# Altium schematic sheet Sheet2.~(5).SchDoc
size A3; SheetNumber: 1; SheetTotal: 1
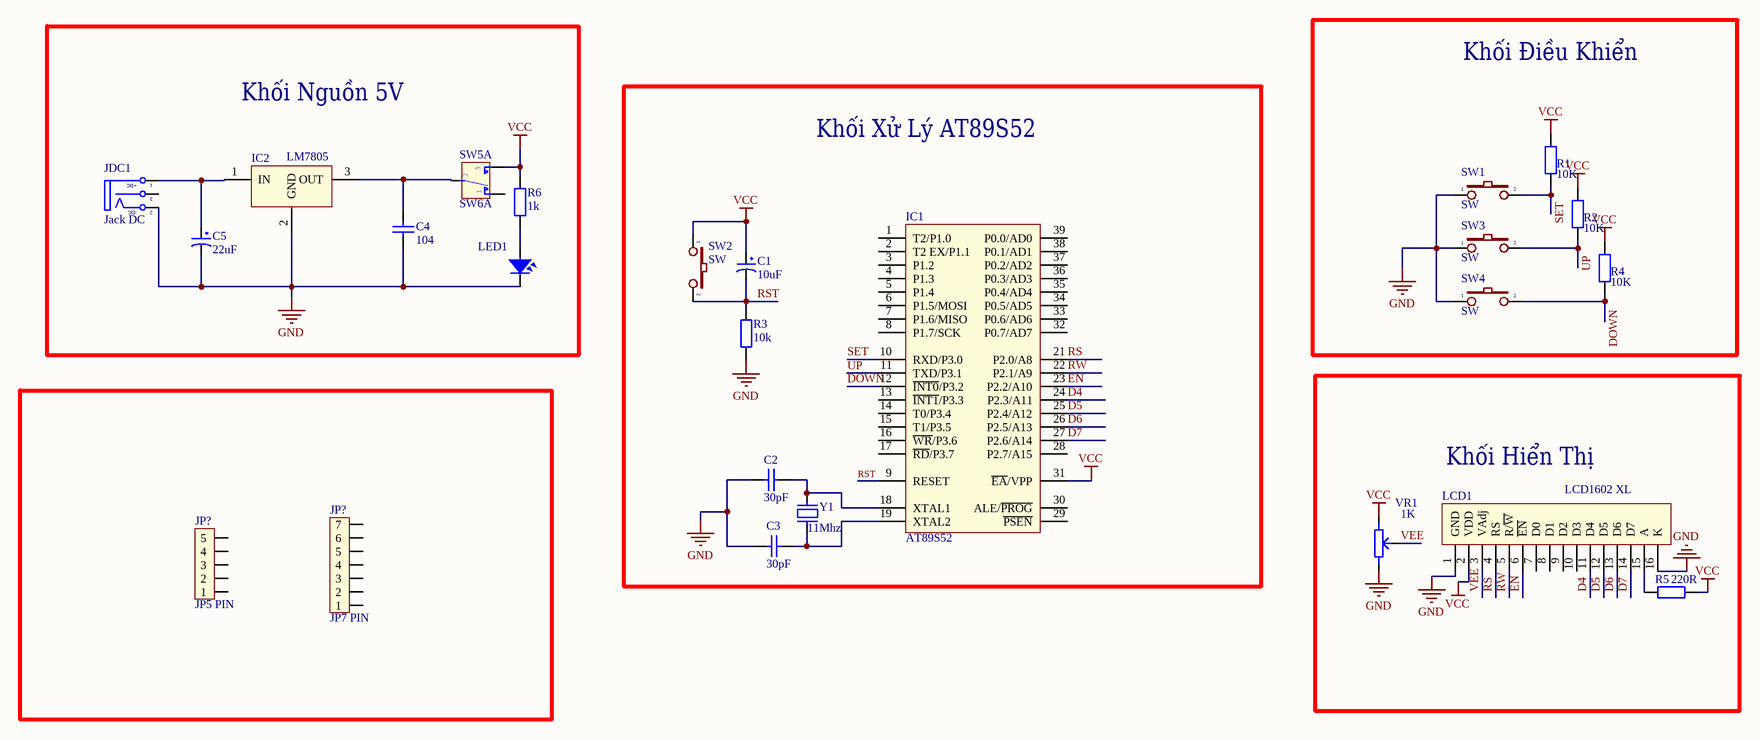
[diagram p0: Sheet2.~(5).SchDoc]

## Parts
(Parts that share a designator on the sheet are numbered #1, #2 ... from top to bottom, then left to right.)
C1  10uF  [tu hoa 4mm]
C2  30pF  [tu gom]
C3  30pF  [tu gom]
C4  104  [tu gom]
C5  22uF  [tu hoa 5mm]
IC1  AT89S52  [DIP40/W0.6]
IC2  LM7805  [QTO-220]
JDC1  Jack DC  [DC-IN]
JP?#1  JP7 PIN  [JP7_1]
JP?#2  JP5 PIN  [JP5_1]
LCD1  LCD1602 XL  [LCD1602 with Jump]
LED1  LED  [LED-5-RED]  (value not drawn)
R1  10K  [tro vach 1/4w]
R2  10K  [tro vach 1/4w]
R3  10k  [tro vach 1/4w]
R4  10K  [tro vach 1/4w]
R5  220R  [tro vach 1/4w]
R6  1k  [R1/4W]
SW1  SW  [SW2]
SW2  SW  [SW2]
SW3  SW  [SW2]
SW4  SW  [SW2]
SW5  SW6A  [SW6]  (part A of 2)
VR1  1K  [Bien Tro Tam Giac Dung]
Y1  11Mhz  [Thach Anh 2 chan cam]

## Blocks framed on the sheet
Khối Điều Khiển: R1 R2 R4 SW1 SW3 SW4
Khối Nguồn 5V: C4 C5 IC2 JDC1 LED1 R6 SW5
Khối Xử Lý AT89S52: C1-C3 IC1 R3 SW2 Y1
Khối Hiển Thị: LCD1 R5 VR1

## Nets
GND: C2.2 C3.2 C4.2 C5.2 IC1.20(GND) IC2.2(GND) JDC1.2(TN) LCD1.1(GND) LCD1.16(K) LED1.2 R3.1 SW1.1 SW3.1 SW4.1 VR1.3
VCC: C1.1 IC1.31(~{EA}/VPP) IC1.40(VCC) LCD1.2(VDD) R1.1 R2.1 R4.1 R5.1 R6.2 SW2.1 SW5.3 VR1.1
D4: IC1.24(P2.3/A11) LCD1.11(D4)
D5: IC1.25(P2.4/A12) LCD1.12(D5)
D6: IC1.26(P2.5/A13) LCD1.13(D6)
D7: IC1.27(P2.6/A14) LCD1.14(D7)
DOWN: IC1.12(~{INT0}/P3.2) R4.2 SW4.2
EN: IC1.23(P2.2/A10) LCD1.6(~{EN})
RS: IC1.21(P2.0/A8) LCD1.4(RS)
RST: C1.2 IC1.9(RESET) R3.2 SW2.2
RW: IC1.22(P2.1/A9) LCD1.5(R/~{W})
SET: IC1.10(RXD/P3.0) R1.2 SW1.2
UP: IC1.11(TXD/P3.1) R2.2 SW3.2
VEE: LCD1.3(VAdj) VR1.2
NetC2_1: C2.1 IC1.18(XTAL1) Y1.2
NetC3_1: C3.1 IC1.19(XTAL2) Y1.1
NetC4_1: C4.1 IC2.3(OUT) SW5.2
NetC5_1: C5.1 IC2.1(IN) JDC1.1(T)
NetLCD1_15: LCD1.15(A) R5.2
NetLED1_1: LED1.1 R6.1

Not connected (* = marked no-connect by the designer): IC1 1(T2/P1.0) 2(T2_EX/P1.1) 3(P1.2) 4(P1.3) 5(P1.4) 6(P1.5/MOSI) 7(P1.6/MISO) 8(P1.7/SCK) 13(~{INT1}/P3.3) 14(T0/P3.4) 15(T1/P3.5) 16(~{WR}/P3.6) 17(~{RD}/P3.7) 28(P2.7/A15) 29(~{PSEN}) 30(ALE/~{PROG}) 32(P0.7/AD7) 33(P0.6/AD6) 34(P0.5/AD5) 35(P0.4/AD4) 36(P0.3/AD3) 37(P0.2/AD2) 38(P0.1/AD1) 39(P0.0/AD0); JDC1 3(S); JP?#1 1 2 3 4 5 6 7; JP?#2 1 2 3 4 5; LCD1 7(D0) 8(D1) 9(D2) 10(D3); SW5 1

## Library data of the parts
C1 = Tu Hoa 10uF 25V 4x7: Cắm; So_Chan: 2; Ten_Linh_Kien: Tụ Hóa 10uF 25V 4x7MM; Don_Vi: Con; Ma_Hang: MH001349
C2 C3 = Tu gom 30pF 50V: Cắm; Don_Vi: Con; So_Chan: 2; Ten_Linh_Kien: Tụ gốm 30P; Ma_Hang: MH004772
C4 = Tu gom 104 50V: Cắm; So_Chan: 2; Ten_Linh_Kien: Tụ gốm 104 100nF 50V; Don_Vi: Con; Ma_Hang: MH004761
C5 = Tu Hoa 22uF 50V 5x10: Cắm; Don_Vi: Con; So_Chan: 2; Ten_Linh_Kien: Tụ Hóa 22uF 50V; Ma_Hang: MH001359
IC1 = AT89S52: AT89S52, 8k Byte Flash Memory , 40 Pin
IC2 = LM78xx: On ap +, from + 5 to + 24VDC
JDC1 = DCIN: Jac DC input; Value: Jac DC
JP?#1 = JP7
JP?#2 = JP5
LCD1 = LCD1602 XL: LCD 1602 Xanh Lá; Ten: Màn hình LCD 1602 Xanh Lá; Ma_Hang: 67HZ; NCC: NSHOP; CHIP: HD44780
LED1 = LED: LED Single colour Green and Red; Value: LED 3 ly Single Colour
R1 R2 R4 R5 = Tro Vach 1/4W 5% 220R: Cắm; Don_Vi: Con; So_Chan: 2; Ten_Linh_Kien: Trở Vạch 1/4w 5% 220R; Ma_Hang: MH007300
R3 = Tro Vach 1/4W 5% 10k: Căm; Chung_Loai: Cắm; Don_Vi: Con; So_Chan: 2; Ten_Linh_Kien: Trở Vạch 1/4w 5% 10K; Ma_Hang: MH007354
R6 = R1/4W: Resistor 1/4W; Value: R1/4W - 1K
SW1-SW4 = SW2: Switch button 2 pin; Value: SW chip 2 pin
SW5 = SW6A: SW-DTDP - 6 Pin; Value: SW6
VR1 = Bien tro tam giac 1K Dung: Cắm; Ten_Linh_Kien: Biến Trở Tam Giác 102-1K RM065; Don_Vi: Con; Ma_Hang: MH003709
Y1 = Thach Anh 2 chan Cam: Crystal For all Crystal 2pin.; Value: 4Mhz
